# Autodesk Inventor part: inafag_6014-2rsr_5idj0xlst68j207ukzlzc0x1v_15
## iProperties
Shininess: 64.0
Angle Display Precision: 2
Document Length Units: 11269
Document Angle Units: 11279
Document Time Units: 11290
Document Mass Units: 11283
Document Length Units Precision: 3
Document Angle Units Precision: 2
Compacted: True
Created: 2008-08
Part Number: inafag_6014-2rsr_5idj0xlst68j207ukzlzc0x1v_15
Document SubType Name: Modeling
Designer: tpomodeler
Density: 0.0
Volumn: 0.0
Area: 0.0
PropertySet Name: Model Information
Control State: 0
Master: False
Checked Out: False
Author: tpomodeler
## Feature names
1. inafag_6014-2rsr_5idj0xlst68j207ukzlzc0x1v
